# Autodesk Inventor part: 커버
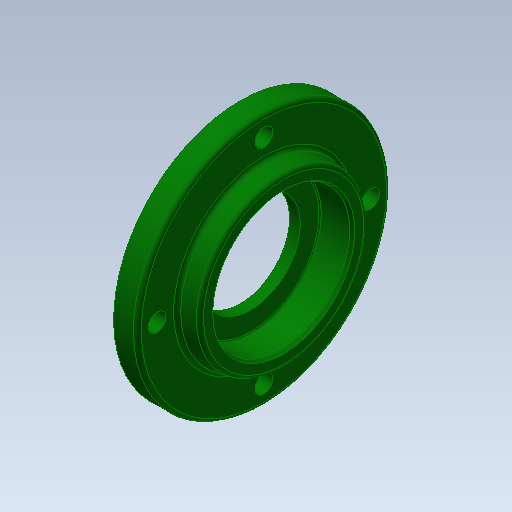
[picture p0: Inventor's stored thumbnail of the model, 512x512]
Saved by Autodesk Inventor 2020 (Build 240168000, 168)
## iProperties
Created: 2018-11
Part Number: 커버
Material: 알루미늄 6061
Document SubType Name: Modeling
Designer: mduedu
Density: 1 g/cm^3
Appearance: 진녹색
Author: mduedu
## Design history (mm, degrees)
sketch "스케치1"
  geometry: L1 (0, 0)-(3, 0); L2 (3, 0)-(3, 23.5); L3 (3, 23.5)-(0, 23.5); L4 (0, 23.5)-(0, 0); L5 (3, 0)-(9, 0); L6 (9, 0)-(9, 32); L7 (9, 32)-(3, 32); L8 (3, 32)-(3, 0); L9 (9, 0)-(14, 0); L10 (14, 0)-(14, 21.118); L11 (9, 22)-(9, 0); L12 (9, 22)-(14, 21.118)
  constraints: 24 end point, 5 parallel, 3 horizontal, 3 perpendicular
  dimensions: "d0" = 64 diameter of L7 L5; "d3" = 47 diameter of L3 L1; "d4" = 3 distance of L2.end L3.end; "d5" = 6 distance of L6.end L7.end; "d6" = 14 distance between parallel lines of L10 L4; "d37" = 44 diameter of L11.start L9; "d38" = 10 deg angle of L9 L12
revolve "회전1" sketch "스케치1" stored, may be unused: angle "d7" = 90 deg
sketch "스케치2"
  geometry: L1 (0, -23.5)-(0, 23.5) reference; L2 (0, 23.5)-(3, 23.5) reference; L3 (3, 23.5)-(3, 32) reference; L4 (3, 32)-(9, 32) reference; L5 (9, 32)-(9, 22) reference; L6 (9, -22)-(9, -32) reference; L7 (9, -32)-(3, -32) reference; L8 (3, -32)-(3, -23.5) reference; L9 (3, -23.5)-(0, -23.5) reference; L10 (0, 0)-(3, 0); L11 (3, 0)-(3, 20); L12 (3, 20)-(0, 20); L13 (0, 20)-(0, 0); L14 (3, 0)-(5.7, 0); L15 (5.7, 0)-(5.7, 12.5); L16 (5.7, 12.5)-(3, 12.5); L17 (3, 12.5)-(3, 0); L18 (5.7, 0)-(14, 0); L19 (14, 0)-(14, 17.5); L20 (14, 17.5)-(5.7, 17.5); L21 (5.7, 17.5)-(5.7, 0); L22 (9, 22)-(14, 21.118) reference; L23 (14, 21.118)-(14, -21.118) reference; L24 (14, -21.118)-(9, -22) reference
  constraints: 24 end point, 6 parallel, 3 horizontal, 3 perpendicular, 1 midpoint
  dimensions: "d8" = 35 diameter of L20 L18; "d10" = 25 diameter of L16 L14; "d11" = 40 diameter of L12 L10; "d12" = 3 distance of L11.end L12.end; "d13" = 8.3 distance of L19.end L20.end
revolve "회전2" sketch "스케치2" stored, may be unused: angle "d14" = 90 deg
fillet "모깎기1" dims "d15" = 0.3
chamfer "모따기1" distance "d16" = 0.8; stored, may be unused: second distance "d17" = 2, angle "d18" = 30 deg
fillet "모깎기2" dims "d19" = 1, "d35" = 3
chamfer "모따기2" distance "d20" = 0.5; stored, may be unused: second distance "d21" = 2, angle "d22" = 30 deg
sketch "스케치3" dims "d23" = 52
  geometry: 6 further points
  constraints: 2 vertical alignment, 1 coincident, 7 other
  dimensions: "d26" = 360 deg dimension on point (0, 0) point (0, 26) (derived)
sketch "스케치4" dims "d39" = 54
  geometry: C1 r 32 at (0, 0) reference; 5 further points
  constraints: 2 vertical alignment, 1 coincident, 7 other
  dimensions: "d43" = 360 deg dimension on C1.centre point (0, 27) (derived)
hole "구멍1" sketch "스케치4" at (0, 27), (-27, 0), (0, -27), (27, 0) diameter "d28" = 4.5; stored, may be unused: countersink angle "d32" = 90 deg, drill point angle "d34" = 0 deg; dims "d29" = 6, "d30" = 8, "d31" = 4.6, "d33" = 8
node "솔리드1"
node "절단 모서리 투영1"
